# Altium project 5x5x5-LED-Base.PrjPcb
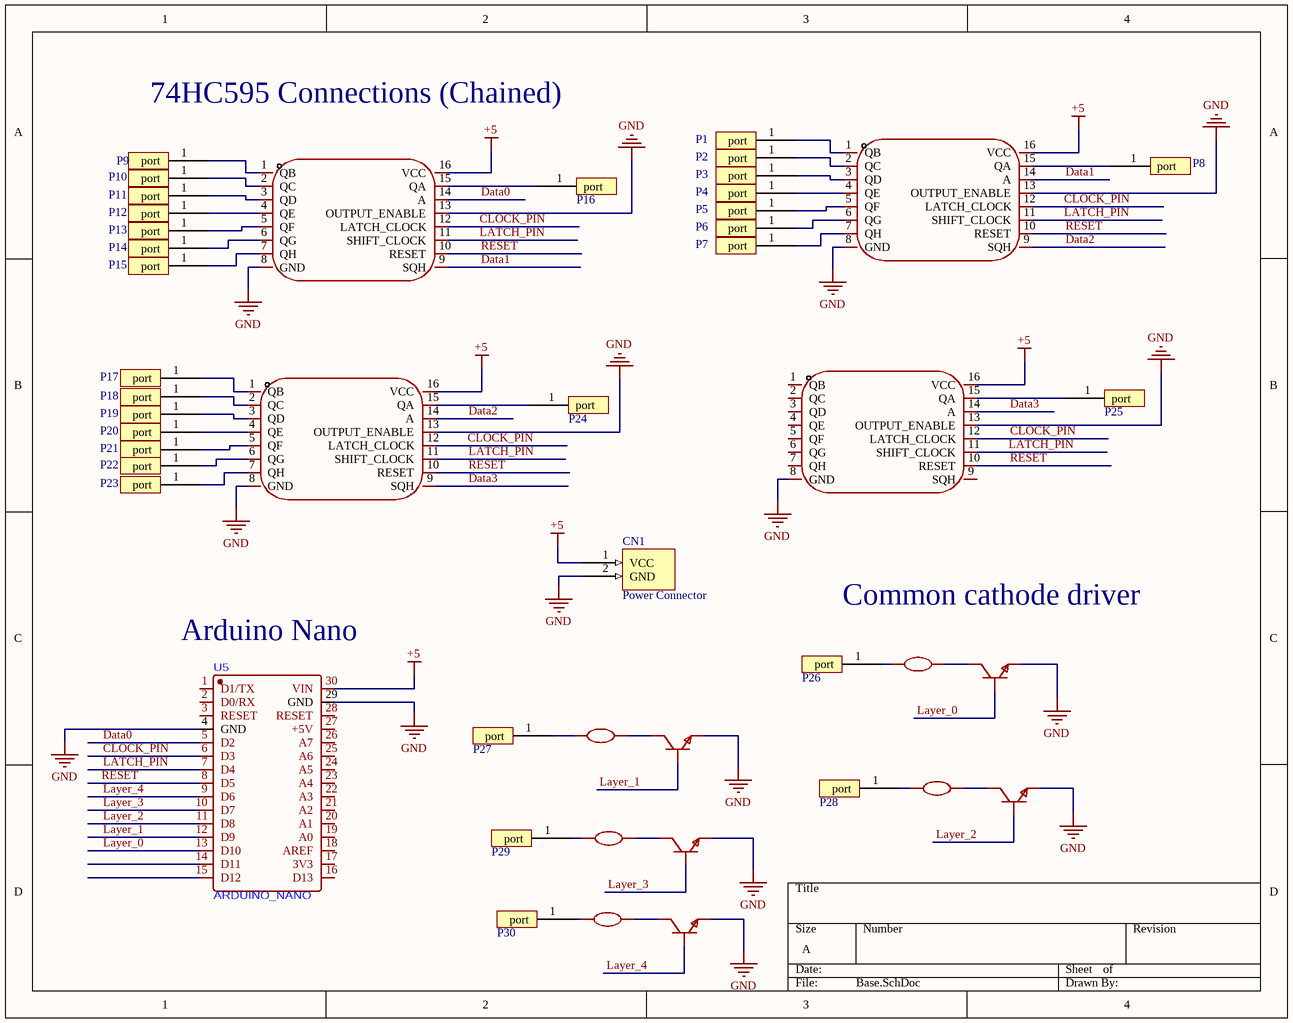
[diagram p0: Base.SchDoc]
1 sheet, 46 parts. Net scope: global (net labels, ports and power ports of the same name join across sheets).
Board file: 5x5x5-LED_base.PcbDoc

## Sheet Base.SchDoc
size A; SheetNumber: 1; SheetTotal: 1

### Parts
CN1  Power Connector  [power port]
P1  Port_1  [port]  (value not drawn)
P2  Port_1  [port]  (value not drawn)
P3  Port_1  [port]  (value not drawn)
P4  Port_1  [port]  (value not drawn)
P5  Port_1  [port]  (value not drawn)
P6  Port_1  [port]  (value not drawn)
P7  Port_1  [port]  (value not drawn)
P8  Port_1  [port]  (value not drawn)
P9  Port_1  [port]  (value not drawn)
P10  Port_1  [port]  (value not drawn)
P11  Port_1  [port]  (value not drawn)
P12  Port_1  [port]  (value not drawn)
P13  Port_1  [port]  (value not drawn)
P14  Port_1  [port]  (value not drawn)
P15  Port_1  [port]  (value not drawn)
P16  Port_1  [port]  (value not drawn)
P17  Port_1  [port]  (value not drawn)
P18  Port_1  [port]  (value not drawn)
P19  Port_1  [port]  (value not drawn)
P20  Port_1  [port]  (value not drawn)
P21  Port_1  [port]  (value not drawn)
P22  Port_1  [port]  (value not drawn)
P23  Port_1  [port]  (value not drawn)
P24  Port_1  [port]  (value not drawn)
P25  Port_1  [port]  (value not drawn)
P26  Port_1  [port]  (value not drawn)
P27  Port_1  [port]  (value not drawn)
P28  Port_1  [port]  (value not drawn)
P29  Port_1  [port]  (value not drawn)
P30  Port_1  [port]  (value not drawn)
Q1  BC547BTA  [TO-92-3_L4.8-W3.7-P2.54-L]  (value not drawn)
Q2  BC547BTA  [TO-92-3_L4.8-W3.7-P2.54-L]  (value not drawn)
Q3  BC547BTA  [TO-92-3_L4.8-W3.7-P2.54-L]  (value not drawn)
Q4  BC547BTA  [TO-92-3_L4.8-W3.7-P2.54-L]  (value not drawn)
Q5  BC547BTA  [TO-92-3_L4.8-W3.7-P2.54-L]  (value not drawn)
R1  1kΩ  [RES-TH_BD2.7-L6.2-P10.20-D0.4]  (value not drawn)
R2  1kΩ  [RES-TH_BD2.7-L6.2-P10.20-D0.4]  (value not drawn)
R3  1kΩ  [RES-TH_BD2.7-L6.2-P10.20-D0.4]  (value not drawn)
R4  1kΩ  [RES-TH_BD2.7-L6.2-P10.20-D0.4]  (value not drawn)
R5  1kΩ  [RES-TH_BD2.7-L6.2-P10.20-D0.4]  (value not drawn)
U1  74HC595N  [DIP-16_L20.0-W6.4-P2.54-LS7.6-BL]  (value not drawn)
U2  74HC595N  [DIP-16_L20.0-W6.4-P2.54-LS7.6-BL]  (value not drawn)
U3  74HC595N  [DIP-16_L20.0-W6.4-P2.54-LS7.6-BL]  (value not drawn)
U4  74HC595N  [DIP-16_L20.0-W6.4-P2.54-LS7.6-BL]  (value not drawn)
U5  ARDUINO_NANO  [ARDUINO NANO.]

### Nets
+5: CN1.1(VCC) U1.16(VCC) U2.16(VCC) U3.16(VCC) U4.16(VCC) U5.30(VIN)
GND: CN1.2(GND) Q1.3(E) Q2.3(E) Q3.3(E) Q4.3(E) Q5.3(E) U1.8(GND) U1.13(OUTPUT_ENABLE) U2.8(GND) U2.13(OUTPUT_ENABLE) U3.8(GND) U3.13(OUTPUT_ENABLE) U4.8(GND) U4.13(OUTPUT_ENABLE) U5.4(GND) U5.29(GND)
CLOCK_PIN: U1.12(LATCH_CLOCK) U2.12(LATCH_CLOCK) U3.12(LATCH_CLOCK) U4.12(LATCH_CLOCK) U5.6(D3)
Data0: U2.14(A) U5.5(D2)
Data1: U1.14(A) U2.9(SQH)
Data2: U1.9(SQH) U4.14(A)
Data3: U3.14(A) U4.9(SQH)
LATCH_PIN: U1.11(SHIFT_CLOCK) U2.11(SHIFT_CLOCK) U3.11(SHIFT_CLOCK) U4.11(SHIFT_CLOCK) U5.7(D4)
Layer_0: Q1.2(B) U5.13(D10)
Layer_1: Q2.2(B) U5.12(D9)
Layer_2: Q3.2(B) U5.11(D8)
Layer_3: Q4.2(B) U5.10(D7)
Layer_4: Q5.2(B) U5.9(D6)
RESET: U1.10(RESET) U2.10(RESET) U3.10(RESET) U4.10(RESET) U5.8(D5)
NetP1_1: P1.1(port) U1.1(QB)
NetP2_1: P2.1(port) U1.2(QC)
NetP3_1: P3.1(port) U1.3(QD)
NetP4_1: P4.1(port) U1.4(QE)
NetP5_1: P5.1(port) U1.5(QF)
NetP6_1: P6.1(port) U1.6(QG)
NetP7_1: P7.1(port) U1.7(QH)
NetP8_1: P8.1(port) U1.15(QA)
NetP9_1: P9.1(port) U2.1(QB)
NetP10_1: P10.1(port) U2.2(QC)
NetP11_1: P11.1(port) U2.3(QD)
NetP12_1: P12.1(port) U2.4(QE)
NetP13_1: P13.1(port) U2.5(QF)
NetP14_1: P14.1(port) U2.6(QG)
NetP15_1: P15.1(port) U2.7(QH)
NetP16_1: P16.1(port) U2.15(QA)
NetP17_1: P17.1(port) U4.1(QB)
NetP18_1: P18.1(port) U4.2(QC)
NetP19_1: P19.1(port) U4.3(QD)
NetP20_1: P20.1(port) U4.4(QE)
NetP21_1: P21.1(port) U4.5(QF)
NetP22_1: P22.1(port) U4.6(QG)
NetP23_1: P23.1(port) U4.7(QH)
NetP24_1: P24.1(port) U4.15(QA)
NetP25_1: P25.1(port) U3.15(QA)
NetP26_1: P26.1(port) R1.1
NetP27_1: P27.1(port) R2.1
NetP28_1: P28.1(port) R3.1
NetP29_1: P29.1(port) R4.1
NetP30_1: P30.1(port) R5.1
NetQ1_1: Q1.1(C) R1.2
NetQ2_1: Q2.1(C) R2.2
NetQ3_1: Q3.1(C) R3.2
NetQ4_1: Q4.1(C) R4.2
NetQ5_1: Q5.1(C) R5.2

Not connected (* = marked no-connect by the designer): U3 1(QB) 2(QC) 3(QD) 4(QE) 5(QF) 6(QG) 7(QH) 9(SQH); U5 1(D1/TX) 2(D0/RX) 3(RESET) 14(D11) 15(D12) 16(D13) 17(3V3) 18(AREF) 19(A0) 20(A1) 21(A2) 22(A3) 23(A4) 24(A5) 25(A6) 26(A7) 27(+5V) 28(RESET)

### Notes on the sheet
- 74HC595 Connections (Chained)
- Common cathode driver
- (near U5) Arduino Nano

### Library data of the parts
Q1-Q5 = BC547BTA: Manufacturer: onsemi(安森美); Add into BOM: yes; DC Current Gain (hFE@Ic,Vce): 110@2mA,5V; Transition Frequency (fT): 300MHz; Collector Cut-Off Current (Icbo): 15nA; Collector-Emitter Saturation Voltage (VCE(sat)@Ic,Ib): 90mV@10mA,0.5mA
R1-R5 = MF1/4W-1K±1%-ST52: Manufacturer: VO(翔胜); Add into BOM: yes; Tolerance: ±1%; Overload Voltage (Max): 250V; Power(Watts): 250mW; Temperature Coefficient: ±100ppm/℃
U1-U4 = 74HC595N_C507175: Manufacturer: HGSEMI(华冠); Add into BOM: yes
